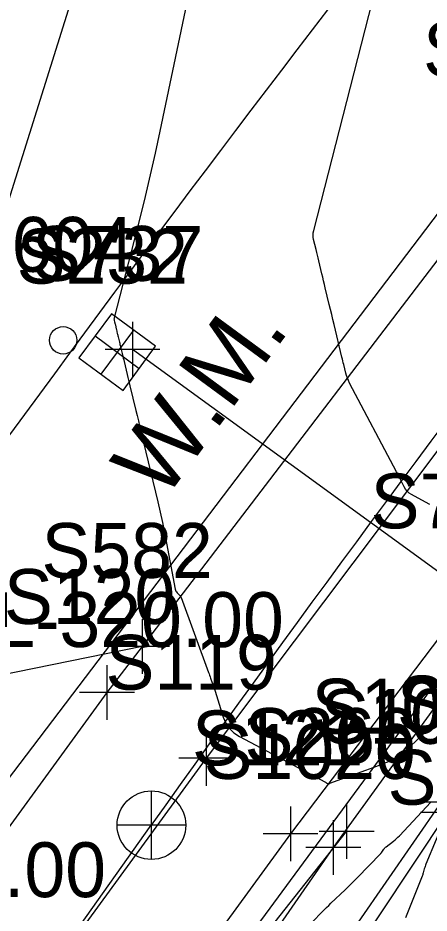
# Model space of a CAD drawing. Extents: x 816928 to 825690, y 436959 to 448212.
# Drawn here: x 819193.5 to 819223.5, y 445500 to 445565.3 of the extents above; entities that cross this region are included whole.
import ezdxf

# ---------------------------------------------------------------- set-up
doc = ezdxf.new("R2010")
doc.units = 0
for name, color, linetype in [('SURVEY - CENTERLINE - Preliminary', 7, 'Continuous'), ('SURVEY - CENTERLINE - Preliminary - Development', 7, 'Continuous'), ('SURVEY - CENTERLINE - Preliminary Text', 7, 'Continuous'), ('SURVEY - CONTOURS - Intermediate with optional Text', 7, 'Continuous'), ('SURVEY - DRAINAGE - Area Shapes', 7, 'Continuous'), ('SURVEY - DTM - Breaklines', 7, 'Continuous'), ('SURVEY - DTM - Breaklines - Points - Locators', 7, 'Continuous'), ('SURVEY - DTM - Breaklines - Points - Numbers', 7, 'Continuous'), ('SURVEY - DTM - Spot Points - Locators', 7, 'Continuous'), ('SURVEY - DTM - Spot Points - Point Numbers', 7, 'Continuous'), ('SURVEY - PROPERTY - Parcels', 7, 'Continuous'), ('SURVEY - PROPERTY - Property Lines - Points - Elevations', 7, 'Continuous'), ('SURVEY - PROPERTY - ROW Lines', 7, 'Continuous'), ('SURVEY - PROPERTY - Station and Offset Flags', 7, 'Continuous'), ('SURVEY - TRANSPORTATION - Features', 7, 'Continuous'), ('SURVEY - TRANSPORTATION - Features - Points - Locators', 7, 'Continuous'), ('SURVEY - TRANSPORTATION - Features - Points - Numbers', 7, 'Continuous'), ('SURVEY - TRANSPORTATION - Roads', 7, 'Continuous'), ('SURVEY - TRANSPORTATION - Roads - Points - Locators', 7, 'Continuous'), ('SURVEY - TRANSPORTATION - Roads - Points - Numbers', 7, 'Continuous'), ('SURVEY - UTILITIES - Gas with Text', 7, 'Continuous'), ('SURVEY - UTILITIES - Water - Points - Locators', 7, 'Continuous'), ('SURVEY - UTILITIES - Water - Points - Numbers', 7, 'Continuous'), ('SURVEY - UTILITIES - Water with Text', 7, 'Continuous'), ('SURVEY - VEGETATION - Features - Points - Locators', 7, 'Continuous'), ('SURVEY - VEGETATION - Features - Points - Numbers', 7, 'Continuous'), ('SURVEY - VEGETATION - Features with Text', 7, 'Continuous')]:
    doc.layers.add(name, color=color, linetype=linetype)

msp = doc.modelspace()

# ---------------------------------------------------------------- linework, layer by layer
at = {"layer": 'SURVEY - CENTERLINE - Preliminary'}
msp.add_line((818959.546, 445163.523), (819203.252, 445506.431), dxfattribs=at)
msp.add_arc((820425.92, 444637.477), 1500, 140.141729, 144.598464, dxfattribs=at)
msp.add_arc((820425.92, 444637.477), 1500, 140.141729, 144.598464, dxfattribs=at)
at = {"layer": 'SURVEY - CENTERLINE - Preliminary - Development'}
for p, q in [((819203.252, 445508.931), (819203.252, 445503.931)), ((819205.752, 445506.431), (819200.752, 445506.431))]:
    msp.add_line(p, q, dxfattribs=at)
at = {"layer": 'SURVEY - CENTERLINE - Preliminary Text'}
msp.add_line((819203.252, 445506.431), (819203.252, 445506.431), dxfattribs=at)
msp.add_circle((819203.271, 445506.437), 2.5, dxfattribs=at)
at = {"layer": 'SURVEY - CONTOURS - Intermediate with optional Text'}
for points in [[(819213.152, 445601.193), (819203.888, 445557.046), (819203.545, 445555.456), (819203.185, 445553.87), (819202.807, 445552.288), (819202.413, 445550.711), (819200.553, 445543.446), (819200.544, 445543.401), (819200.541, 445543.357), (819200.543, 445543.312), (819200.551, 445543.267), (819200.587, 445543.121), (819200.594, 445543.09), (819200.602, 445543.059), (819200.609, 445543.027), (819200.617, 445542.996), (819200.67, 445542.774), (819200.682, 445542.727), (819200.693, 445542.679), (819200.704, 445542.632), (819200.716, 445542.584), (819200.784, 445542.301), (819200.799, 445542.241), (819200.813, 445542.18), (819200.828, 445542.119), (819200.842, 445542.059), (819200.937, 445541.663), (819200.958, 445541.579), (819200.978, 445541.494), (819200.999, 445541.409), (819201.019, 445541.325), (819201.159, 445540.742), (819201.189, 445540.617), (819201.219, 445540.492), (819201.249, 445540.367), (819201.279, 445540.242), (819201.507, 445539.296), (819201.556, 445539.093), (819201.605, 445538.89), (819201.654, 445538.687), (819201.702, 445538.485), (819202.134, 445536.69), (819202.227, 445536.305), (819202.32, 445535.92), (819202.412, 445535.536), (819202.505, 445535.151), (819203.741, 445530.015), (819203.915, 445529.268), (819204.08, 445528.519), (819204.235, 445527.768), (819204.38, 445527.015), (819205.005, 445523.643), (819205.024, 445523.572), (819205.053, 445523.505), (819205.092, 445523.444), (819205.141, 445523.389), (819205.319, 445523.217), (819205.354, 445523.178), (819205.385, 445523.136), (819205.41, 445523.091), (819205.431, 445523.043), (819207.437, 445517.572), (819207.475, 445517.47), (819207.513, 445517.367), (819207.55, 445517.265), (819207.588, 445517.162), (819207.711, 445516.827), (819207.736, 445516.755), (819207.762, 445516.683), (819207.786, 445516.61), (819207.809, 445516.538), (819208.513, 445514.319), (819208.7, 445513.874), (819208.959, 445513.489), (819209.291, 445513.164), (819209.695, 445512.899), (819215.962, 445509.561), (819215.986, 445509.548), (819216.011, 445509.535), (819216.035, 445509.522), (819216.06, 445509.509), (819216.164, 445509.454), (819216.169, 445509.452), (819216.175, 445509.451), (819216.18, 445509.451), (819216.186, 445509.452), (819216.204, 445509.459), (819216.208, 445509.46), (819216.212, 445509.462), (819216.216, 445509.463), (819216.22, 445509.465), (819216.258, 445509.479), (819216.266, 445509.482), (819216.274, 445509.485), (819216.283, 445509.488), (819216.291, 445509.491), (819218.895, 445510.445), (819219.169, 445510.546), (819219.443, 445510.649), (819219.716, 445510.752), (819219.989, 445510.857), (819220.879, 445511.201), (819221.065, 445511.283), (819221.24, 445511.381), (819221.404, 445511.497), (819221.558, 445511.629), (819222.549, 445512.567), (819222.598, 445512.613), (819222.645, 445512.659), (819222.693, 445512.706), (819222.741, 445512.753), (819222.895, 445512.906), (819222.928, 445512.939), (819222.961, 445512.972), (819222.995, 445513.005), (819223.028, 445513.037), (819225.559, 445515.455)], [(819223.56, 445529.827), (819223.262, 445529.988), (819222.228, 445530.549), (819222.06, 445530.656), (819221.915, 445530.785), (819221.792, 445530.936), (819221.692, 445531.108), (819221.4, 445531.704), (819221.337, 445531.832), (819221.273, 445531.959), (819221.208, 445532.085), (819221.142, 445532.211), (819217.718, 445538.684), (819217.632, 445538.859), (819217.557, 445539.039), (819217.494, 445539.223), (819217.443, 445539.412), (819217.293, 445540.035), (819217.261, 445540.168), (819217.229, 445540.301), (819217.197, 445540.435), (819217.164, 445540.568), (819216.593, 445542.943), (819216.504, 445543.312), (819216.415, 445543.681), (819216.327, 445544.05), (819216.238, 445544.418), (819215.948, 445545.623), (819215.886, 445545.881), (819215.824, 445546.14), (819215.761, 445546.398), (819215.699, 445546.656), (819215.471, 445547.603), (819215.423, 445547.806), (819215.374, 445548.009), (819215.325, 445548.212), (819215.276, 445548.415), (819215.097, 445549.159), (819215.068, 445549.318), (819215.06, 445549.478), (819215.071, 445549.637), (819215.102, 445549.796), (819228.248, 445601.144)], [(819215.015, 445499.384), (819215.732, 445500.119), (819215.887, 445500.276), (819216.043, 445500.431), (819216.2, 445500.585), (819216.359, 445500.737), (819217.403, 445501.724), (819217.625, 445501.936), (819217.844, 445502.152), (819218.061, 445502.37), (819218.276, 445502.591), (819219.993, 445504.379), (819220.002, 445504.387), (819220.01, 445504.396), (819220.019, 445504.404), (819220.028, 445504.412), (819220.056, 445504.439), (819220.062, 445504.445), (819220.068, 445504.451), (819220.073, 445504.457), (819220.078, 445504.464), (819220.225, 445504.694), (819220.259, 445504.741), (819220.296, 445504.785), (819220.337, 445504.826), (819220.382, 445504.863), (819220.919, 445505.271), (819221.033, 445505.36), (819221.142, 445505.454), (819221.247, 445505.553), (819221.348, 445505.656), (819223.641, 445508.103)], [(819224.781, 445507.199), (819223.289, 445503.602), (819223.255, 445503.516), (819223.224, 445503.429), (819223.195, 445503.341), (819223.169, 445503.252), (819223.089, 445502.96), (819223.071, 445502.897), (819223.051, 445502.836), (819223.03, 445502.775), (819223.007, 445502.714), (819221.804, 445499.674)]]:
    msp.add_lwpolyline(points, dxfattribs=at)
at = {"layer": 'SURVEY - DRAINAGE - Area Shapes'}
msp.add_line((818959.546, 445163.523), (819203.252, 445506.431), dxfattribs=at)
msp.add_arc((820425.92, 444637.477), 1500, 140.141729, 144.598464, dxfattribs=at)
at = {"layer": 'SURVEY - DTM - Breaklines'}
for points in [[(819380.404, 445755.141), (819355.578, 445711.888), (819328.616, 445669.931), (819299.268, 445629.736), (819268.215, 445590.476), (819237.204, 445551.148), (819207.272, 445511.316), (819178.097, 445471.355), (819148.961, 445430.516), (819120.831, 445389.41), (819092.595, 445348.525), (819063.764, 445307.701), (819034.576, 445266.965), (819005.716, 445226.512), (818977.706, 445187.397)], [(819115.743, 445352.623), (819116.501, 445348.532), (819118.762, 445346.334), (819121.805, 445346.034), (819151.273, 445387.488), (819170.031, 445419.1), (819198.511, 445465.669), (819205.76, 445465.616), (819229.822, 445502.933), (819247.854, 445531.915), (819280.031, 445574.26), (819278.221, 445576.151), (819274.311, 445579.267), (819242.916, 445541.289), (819216.533, 445504.811), (819186.916, 445462.104), (819160.05, 445422.329), (819116.797, 445352.316)], [(819118.629, 445350.898), (819165.289, 445424.101), (819196.182, 445467.268), (819224.41, 445508.114), (819242.999, 445536.052), (819276.537, 445576.778)], [(819121.197, 445348.347), (819148.072, 445388.457), (819146.917, 445389.221), (819167.079, 445422.999), (819197.484, 445466.128), (819224.892, 445507.372), (819245.683, 445533.866), (819277.871, 445575.058)]]:
    msp.add_lwpolyline(points, dxfattribs=at)
at = {"layer": 'SURVEY - DTM - Breaklines - Points - Locators'}
for p, q in [((819207.272, 445513.316), (819207.272, 445509.316)), ((819209.272, 445511.316), (819205.272, 445511.316)), ((819226.41, 445508.114), (819222.41, 445508.114)), ((819226.892, 445507.372), (819222.892, 445507.372)), ((819216.533, 445506.811), (819216.533, 445502.811)), ((819218.533, 445504.811), (819214.533, 445504.811))]:
    msp.add_line(p, q, dxfattribs=at)
at = {"layer": 'SURVEY - DTM - Spot Points - Locators'}
msp.add_circle((819196.839, 445541.798), 1, dxfattribs=at)
at = {"layer": 'SURVEY - PROPERTY - Parcels'}
msp.add_arc((820425.92, 444637.477), 1525, 140.141729, 144.574738, dxfattribs=at)
at = {"layer": 'SURVEY - PROPERTY - ROW Lines'}
msp.add_arc((820425.92, 444637.477), 1525, 140.141729, 144.574738, dxfattribs=at)
msp.add_arc((820425.92, 444637.477), 1525, 140.141729, 144.574738, dxfattribs=at)
at = {"layer": 'SURVEY - PROPERTY - Station and Offset Flags'}
msp.add_lwpolyline([(819207.521, 445598.873), (819183.24, 445521.428)], dxfattribs=at)
at = {"layer": 'SURVEY - TRANSPORTATION - Features'}
msp.add_lwpolyline([(819202.59, 445519.473), (819184.071, 445515.709), (819131.801, 445523.942), (819076.994, 445531.354), (819016.138, 445540.636)], dxfattribs=at)
at = {"layer": 'SURVEY - TRANSPORTATION - Features - Points - Locators'}
for p, q in [((819202.59, 445521.473), (819202.59, 445517.473)), ((819204.59, 445519.473), (819200.59, 445519.473))]:
    msp.add_line(p, q, dxfattribs=at)
at = {"layer": 'SURVEY - TRANSPORTATION - Roads'}
for points in [[(819372.417, 445760.729), (819347.536, 445716.465), (819327.358, 445684.931), (819320.732, 445674.576), (819313.086, 445663.907), (819291.72, 445634.092), (819261.573, 445595.794), (819230.52, 445556.026), (819202.59, 445519.473), (819200.025, 445516.115), (819183.78, 445493.817), (819171.491, 445476.948), (819142.501, 445435.003), (819121.554, 445405.003), (819114.313, 445394.631), (819108.813, 445386.861), (819085.629, 445354.103), (819056.538, 445311.65), (819028.029, 445272.038), (818998.985, 445231.035), (818970.783, 445191.785), (818984.089, 445181.723)], [(819389.734, 445754.855), (819362.957, 445707.555), (819358.085, 445699.888), (819346.624, 445681.852), (819335.583, 445664.476), (819305.378, 445623.327), (819290.371, 445604.569), (819280.694, 445592.472), (819274.745, 445585.035), (819271.707, 445581.193), (819243.267, 445545.212), (819213.411, 445505.8), (819184.164, 445465.705), (819155.799, 445425.75), (819127.747, 445384.791), (819108.123, 445356.526), (819098.861, 445343.186), (819090.273, 445331.1), (819070.114, 445302.733), (819042.351, 445263.277), (819039.074, 445258.681), (819026.695, 445241.322), (819012.76, 445221.779), (818984.089, 445181.723)]]:
    msp.add_lwpolyline(points, dxfattribs=at)
at = {"layer": 'SURVEY - TRANSPORTATION - Roads - Points - Locators'}
for p, q in [((819200.025, 445518.115), (819200.025, 445514.115)), ((819202.025, 445516.115), (819198.025, 445516.115)), ((819213.411, 445507.8), (819213.411, 445503.8)), ((819215.411, 445505.8), (819211.411, 445505.8))]:
    msp.add_line(p, q, dxfattribs=at)
at = {"layer": 'SURVEY - UTILITIES - Gas with Text'}
msp.add_lwpolyline([(818968.105, 445195.328), (818969.738, 445197.267), (819012.001, 445253.658), (819064.107, 445326.037), (819122.078, 445408.8), (819183.152, 445497.068), (819237.635, 445568.809), (819293.129, 445639.42), (819349.073, 445723.122), (819383.091, 445785.202)], dxfattribs=at)
at = {"layer": 'SURVEY - UTILITIES - Water - Points - Locators'}
for p, q in [((819201.889, 445543.139), (819201.889, 445539.139)), ((819201.959, 445542.547), (819199.589, 445539.325)), ((819199.163, 445542.121), (819202.385, 445539.751)), ((819203.889, 445541.139), (819199.889, 445541.139))]:
    msp.add_line(p, q, dxfattribs=at)
at = {"layer": 'SURVEY - UTILITIES - Water with Text'}
for p, q in [((819200.774, 445540.936), (819200.774, 445540.936)), ((819226.696, 445523.083), (819201.889, 445541.139))]:
    msp.add_line(p, q, dxfattribs=at)
for points in [[(818803.235, 444799.745), (818822.09, 444847.157), (818840.807, 444894.989), (818859.419, 444943.113), (818878.417, 444989.731), (818897.247, 445035.659), (818918.394, 445078.737), (818943.016, 445121.017), (818943.424, 445156.253), (818947.564, 445166.115), (818971.795, 445201.192), (819041.117, 445261.897), (819085.564, 445324.056), (819114.437, 445364.745), (819142.589, 445406.123), (819261.281, 445567.542), (819325.961, 445650.567), (819357.336, 445697.813), (819381.766, 445739.87), (819404.905, 445782.998)], [(819197.977, 445540.51), (819201.2, 445538.139), (819203.57, 445541.362), (819200.348, 445543.732), (819197.977, 445540.51)]]:
    msp.add_lwpolyline(points, dxfattribs=at)
at = {"layer": 'SURVEY - VEGETATION - Features - Points - Locators'}
for p, q in [((819217.5, 445507.972), (819217.5, 445503.972)), ((819219.5, 445505.972), (819215.5, 445505.972))]:
    msp.add_line(p, q, dxfattribs=at)
at = {"layer": 'SURVEY - VEGETATION - Features with Text'}
msp.add_lwpolyline([(819171.253, 445437.696), (819183.062, 445462.383), (819217.5, 445505.972)], dxfattribs=at)

# ---------------------------------------------------------------- texts
at = {"layer": 'SURVEY - DTM - Breaklines - Points - Numbers'}
for s, p in [('S119', (819199.921, 445516.316)), ('S1010', (819214.949, 445513.114)), ('S1009', (819215.588, 445512.372)), ('S1020', (819207.072, 445509.811)), ('S1008', (819220.487, 445507.933))]:
    msp.add_text(s, height=4, dxfattribs=at).set_placement(p)
at = {"layer": 'SURVEY - DTM - Spot Points - Point Numbers'}
msp.add_text('S604', height=4, dxfattribs=at).set_placement((819189.503, 445546.798))
at = {"layer": 'SURVEY - PROPERTY - Property Lines - Points - Elevations'}
for s, p in [('EL-320.00', (819188.24, 445519.428)), ('EL-315.00', (819175.276, 445501.188))]:
    msp.add_text(s, height=4, dxfattribs=at).set_placement(p)
at = {"layer": 'SURVEY - TRANSPORTATION - Features - Points - Numbers'}
msp.add_text('S582', height=4, dxfattribs=at).set_placement((819195.254, 445524.473))
at = {"layer": 'SURVEY - TRANSPORTATION - Roads - Points - Numbers'}
for s, p in [('S116', (819223.074, 445561.026)), ('S120', (819192.516, 445521.115)), ('S121', (819206.233, 445510.8))]:
    msp.add_text(s, height=4, dxfattribs=at).set_placement(p)
at = {"layer": 'SURVEY - UTILITIES - Water - Points - Numbers'}
for s, p in [('S232', (819193.438, 445545.936)), ('S737', (819194.553, 445546.139)), ('S736', (819219.25, 445528.083))]:
    msp.add_text(s, height=4, dxfattribs=at).set_placement(p)
at = {"layer": 'SURVEY - UTILITIES - Water with Text'}
msp.add_text('W.M.', height=5.0001, rotation=53.66241, dxfattribs=at).set_placement((819204.155, 445530.007))
at = {"layer": 'SURVEY - VEGETATION - Features - Points - Numbers'}
for s, p in [('S267', (819221.169, 445513.335)), ('S266', (819210.054, 445510.972))]:
    msp.add_text(s, height=4, dxfattribs=at).set_placement(p)

doc.saveas('drawing.dxf')
